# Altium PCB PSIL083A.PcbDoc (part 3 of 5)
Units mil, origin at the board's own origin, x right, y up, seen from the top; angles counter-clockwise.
Board outline 8750 x 2700 mil, 4 copper layers (Top Layer, Signal Layer 1, Signal Layer 2, Bottom Layer), stack 61.2 mil thick; 463 components, 395 nets, 2267 pads, 745 vias.
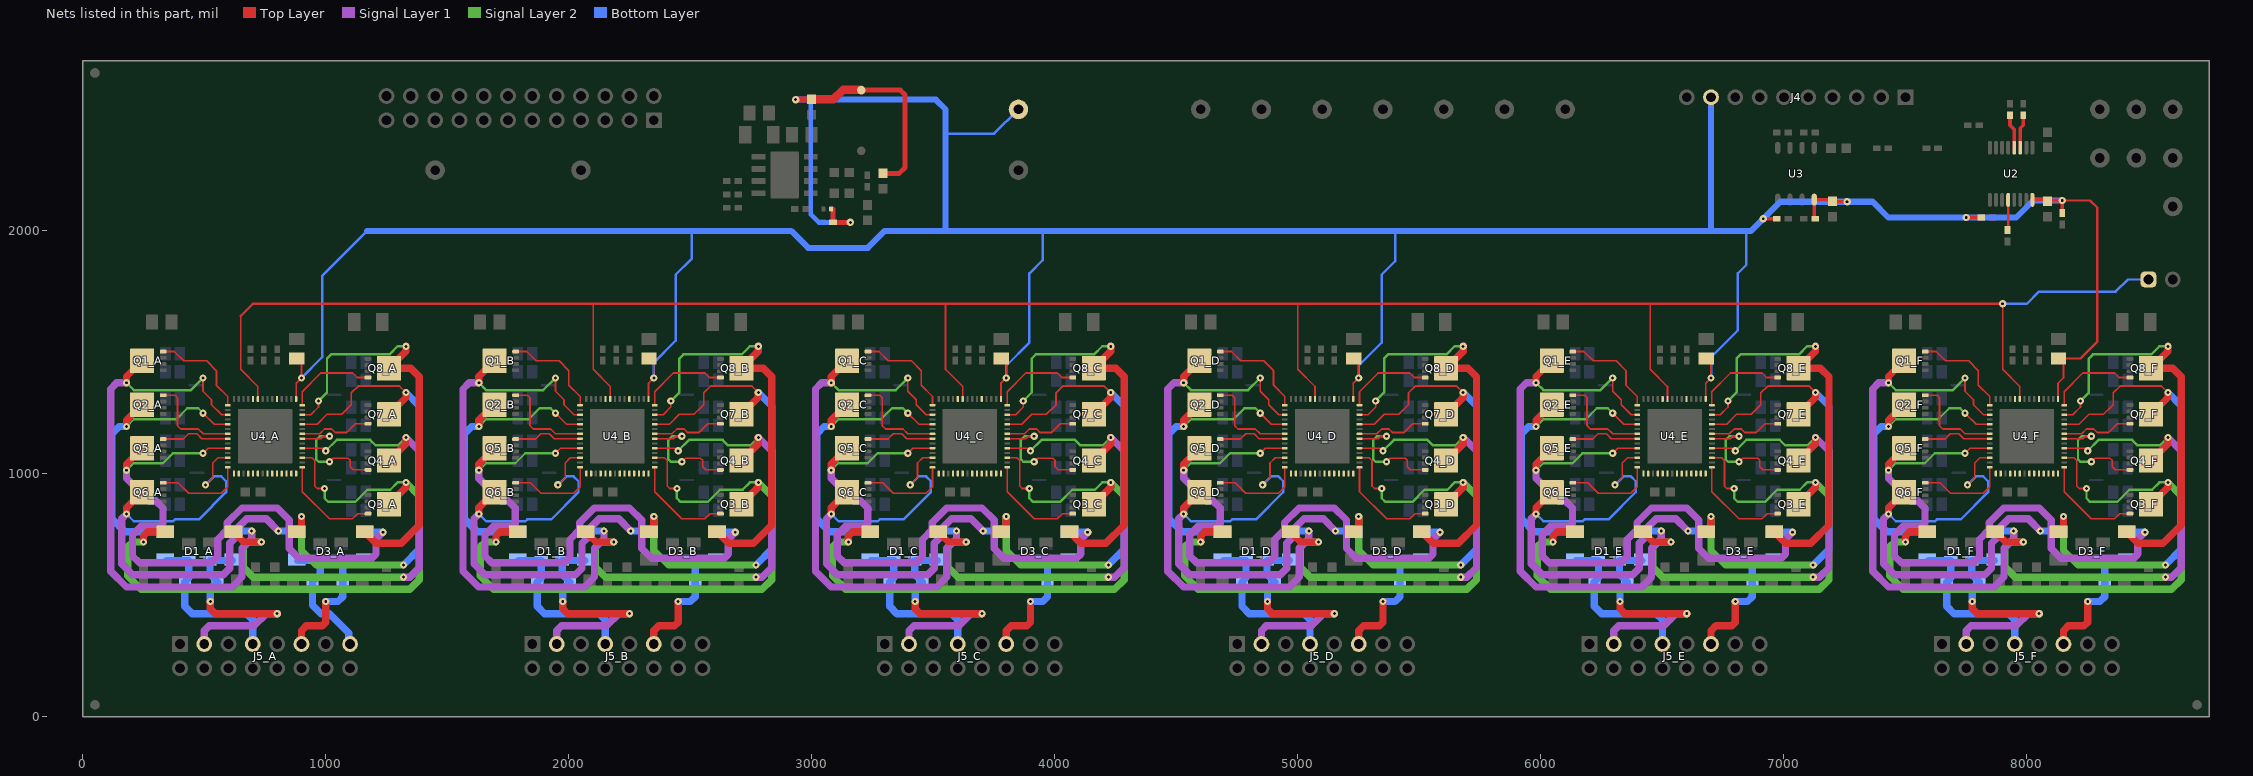
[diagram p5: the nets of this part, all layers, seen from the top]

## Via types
v1: diameter 30, hole 12, Top Layer to Bottom Layer, 610 vias
v2: diameter 19.68, hole 7.87, Top Layer to Bottom Layer, 130 vias
v3: diameter 19.68, hole 7.87, Top Layer to Bottom Layer, tented both sides, 4 vias
v4: diameter 34, hole 16, Top Layer to Bottom Layer, 1 vias

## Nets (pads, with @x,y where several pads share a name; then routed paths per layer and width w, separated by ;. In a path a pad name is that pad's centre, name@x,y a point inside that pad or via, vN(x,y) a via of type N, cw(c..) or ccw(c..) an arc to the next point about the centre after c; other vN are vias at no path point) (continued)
NetR36_2: R36.2 U2.3 | length 139.3
  Top Layer w15: U2.3@7972.5,2342.28 7972.5,2422.5 7985,2435 R36.2@7985,2476.38
NetR37_2: R37.2 U2.4 | length 141.3
  Top Layer w15: R37.2@7930,2476.38 7930,2435 7947.5,2417.5 U2.4@7947.5,2342.28
NetR38_1: R38.1 U2.12 | length 125.1
  Top Layer w10: R38.1@7920,2003.62 7922.5,2006.12 U2.12@7922.5,2127.72
NetU4_A_15: U4_A.15
NetU4_A_16: U4_A.16
NetU4_A_18: U4_A.18
NetU4_A_19: U4_A.19
NetU4_A_20: U4_A.20
NetU4_A_22: U4_A.22
NetU4_A_23: U4_A.23
NetU4_A_24: U4_A.24
NetU4_A_25: U4_A.25
NetU4_A_26: U4_A.26
NetU4_A_27: U4_A.27
NetU4_A_28: U4_A.28
NetU4_A_47: U4_A.47
NetU4_A_52: U4_A.52
NetU4_B_15: U4_B.15
NetU4_B_16: U4_B.16
NetU4_B_18: U4_B.18
NetU4_B_19: U4_B.19
NetU4_B_20: U4_B.20
NetU4_B_22: U4_B.22
NetU4_B_23: U4_B.23
NetU4_B_24: U4_B.24
NetU4_B_25: U4_B.25
NetU4_B_26: U4_B.26
NetU4_B_27: U4_B.27
NetU4_B_28: U4_B.28
NetU4_B_47: U4_B.47
NetU4_B_52: U4_B.52
NetU4_C_15: U4_C.15
NetU4_C_16: U4_C.16
NetU4_C_18: U4_C.18
NetU4_C_19: U4_C.19
NetU4_C_20: U4_C.20
NetU4_C_22: U4_C.22
NetU4_C_23: U4_C.23
NetU4_C_24: U4_C.24
NetU4_C_25: U4_C.25
NetU4_C_26: U4_C.26
NetU4_C_27: U4_C.27
NetU4_C_28: U4_C.28
NetU4_C_47: U4_C.47
NetU4_C_52: U4_C.52
NetU4_D_15: U4_D.15
NetU4_D_16: U4_D.16
NetU4_D_18: U4_D.18
NetU4_D_19: U4_D.19
NetU4_D_20: U4_D.20
NetU4_D_22: U4_D.22
NetU4_D_23: U4_D.23
NetU4_D_24: U4_D.24
NetU4_D_25: U4_D.25
NetU4_D_26: U4_D.26
NetU4_D_27: U4_D.27
NetU4_D_28: U4_D.28
NetU4_D_47: U4_D.47
NetU4_D_52: U4_D.52
NetU4_E_15: U4_E.15
NetU4_E_16: U4_E.16
NetU4_E_18: U4_E.18
NetU4_E_19: U4_E.19
NetU4_E_20: U4_E.20
NetU4_E_22: U4_E.22
NetU4_E_23: U4_E.23
NetU4_E_24: U4_E.24
NetU4_E_25: U4_E.25
NetU4_E_26: U4_E.26
NetU4_E_27: U4_E.27
NetU4_E_28: U4_E.28
NetU4_E_47: U4_E.47
NetU4_E_52: U4_E.52
NetU4_F_15: U4_F.15
NetU4_F_16: U4_F.16
NetU4_F_18: U4_F.18
NetU4_F_19: U4_F.19
NetU4_F_20: U4_F.20
NetU4_F_22: U4_F.22
NetU4_F_23: U4_F.23
NetU4_F_24: U4_F.24
NetU4_F_25: U4_F.25
NetU4_F_26: U4_F.26
NetU4_F_27: U4_F.27
NetU4_F_28: U4_F.28
NetU4_F_47: U4_F.47
NetU4_F_52: U4_F.52
PSE_3.3V: C8.1 C10.1 C12.1 C14_A.1 C14_B.1 C14_C.1 C14_D.1 C14_E.1 C14_F.1 C23.1 J4.9 L1.2 R3.1 R7.1 R8.2 R11.2 R12.2 R32.1 TP2.1 U2.16 U3.8 U4_A.43 U4_B.43 U4_C.43 U4_D.43 U4_E.43 U4_F.43 | length 16707.1
  Top Layer w7: U4_A.43@877.95,1308.54 877.95,1372.95 v1(900,1395) 900,1455 C14_A.1@880,1475 ; U4_B.43@2327.95,1308.54 2327.95,1372.95 v1(2350,1395) 2350,1455 C14_B.1@2330,1475 ; U4_C.43@3777.95,1308.54 3777.95,1372.95 v1(3800,1395) 3800,1455 C14_C.1@3780,1475 ; U4_D.43@5227.95,1308.54 5227.95,1372.95 v1(5250,1395) 5250,1455 C14_D.1@5230,1475 ; U4_E.43@6677.95,1308.54 6677.95,1372.95 v1(6700,1395) 6700,1455 C14_E.1@6680,1475 ; U4_F.43@8127.95,1308.54 8127.95,1372.95 8150,1395 8150,1455 C14_F.1@8130,1475
  Top Layer w10: C14_F.1@8130,1475 8220,1475 8290,1545 8290,2095 8260,2125 v1(8145,2125)
  Top Layer w15: v1(6915,2050) R12.2@6971.06,2050 ; R11.2@7128.31,2050 7124.69,2053.62 U3.8@7124.69,2128.7 7192.48,2128.7 C12.1@7199.69,2121.5 ; C12.1@7201.18,2120 v1(7260,2120) ; v1(7750,2055) R32.1@7811.38,2055 ; U2.16@8022.5,2127.72 8078.78,2127.72 C10.1@8085,2121.5 8088.5,2125 v1(8145,2125) R8.2@8145,2073.62
  Top Layer w20: 3086.93,2090 R3.1@3086.93,2035 v1(3158.31,2035) ; L1.2@3203.31,2579.02 3364.29,2579.02 3383.31,2560 3383.31,2260 3359.8,2236.5 C8.1@3293.31,2236.5
  Top Layer w25: v1(2933.31,2540) R7.1@2996.81,2540
  Top Layer w35: R7.1@2998.31,2541.5 3089.8,2541.5 3128.31,2580 3202.32,2580 L1.2@3203.31,2579.02
  Bottom Layer w10: v1(900,1395) 985,1480 985,1815 1170,2000 ; v1(2350,1395) 2350,1458.3 2440.25,1548.55 2440.25,1799.75 2440,1800 2440,1820 2505,1885 2505,2000 ; 3550,2400 3750,2400 TP2.1@3850,2500 ; v1(3800,1395) 3800,1445 3895,1540 3895,1825 3950,1880 3950,2000 ; v1(5250,1395) 5250,1445 5345,1540 5345,1820 5400,1875 5400,2000 ; v1(6700,1395) 6700,1480 6810,1590 6810,1825 6845,1860 6845,2000
  Bottom Layer w20: 2995.59,2538.78 2995.59,2067.72 3028.31,2035 v1(3158.31,2035)
  Bottom Layer w25: 1170,2000 2505,2000 2915,2000 2985,1930 3230,1930 3300,2000 3550,2000 ; v1(2933.31,2540) 3510,2540 3550,2500 3550,2400 3550,2000 ; J4.9@6700,2550 6700,2000 ; v1(8145,2125) 8025,2125 7955,2055 v1(7750,2055) 7430,2055 7365,2120 v1(7260,2120) 6985,2120 v1(6915,2050) 6865,2000 6845,2000 6700,2000 ; 3550,2000 3950,2000 5400,2000 6700,2000
PSE_A4_A: J2.1 U4_A.51 U4_B.51 U4_C.51 U4_D.51 U4_E.51 U4_F.51 | length 10386
  Top Layer w7: 650,1650 650,1430 720.47,1359.53 U4_A.51@720.47,1308.54 ; 2100,1700 2100,1430 2170.47,1359.53 U4_B.51@2170.47,1308.54 ; 3550,1700 3550,1430 3620.47,1359.53 U4_C.51@3620.47,1308.54 ; 5000,1700 5000,1430 5070.47,1359.53 U4_D.51@5070.47,1308.54 ; 6450,1700 6450,1430 6520.47,1359.53 U4_E.51@6520.47,1308.54 ; v1(7900,1700) 7900,1430 7970.47,1359.53 U4_F.51@7970.47,1308.54
  Top Layer w10: 650,1650 700,1700 v1(7900,1700)
  Bottom Layer w10: v1(7900,1700) 8000,1700 8050,1750 8365,1750 8415,1800 J2.1@8500,1800
PSE_D1_A: F1_A.2 Q1_A.5 Q1_A.6 Q1_A.7 Q1_A.8 Q1_A.9@244.61,1465 U4_A.3 | length 2364.4
  Top Layer w7: v1(495,1395) 495,1340 530,1305 530,1285 571.42,1243.58 U4_A.3@596.46,1243.58
  Top Layer w30: v1(180,1375) 180,1400.39 Q1_A.9@244.61,1465
  Signal Layer 1 w30: v1(180,1375) 140.33,1375 115,1349.67 115,600 180,535 615,535 655.43,575.43 655.43,694.17 695,733.74 v1(695,765)
  Signal Layer 2 w10: v1(180,1375) 210,1345 445,1345 v1(495,1395)
  Bottom Layer w30: F1_A.2@620,762.09 622.91,765 v1(695,765)
PSE_D1_B: F1_B.2 Q1_B.5 Q1_B.6 Q1_B.7 Q1_B.8 Q1_B.9@1694.61,1465 U4_B.3 | length 2364.4
  Top Layer w7: v1(1945,1395) 1945,1340 1980,1305 1980,1285 2021.42,1243.58 U4_B.3@2046.46,1243.58
  Top Layer w30: v1(1630,1375) 1630,1400.39 Q1_B.9@1694.61,1465
  Signal Layer 1 w30: v1(1630,1375) 1590.33,1375 1565,1349.67 1565,600 1630,535 2065,535 2105.43,575.43 2105.43,694.17 2145,733.74 v1(2145,765)
  Signal Layer 2 w10: v1(1630,1375) 1660,1345 1895,1345 v1(1945,1395)
  Bottom Layer w30: F1_B.2@2070,762.09 2072.91,765 v1(2145,765)
PSE_D1_C: F1_C.2 Q1_C.5 Q1_C.6 Q1_C.7 Q1_C.8 Q1_C.9@3144.61,1465 U4_C.3 | length 2364.4
  Top Layer w7: v1(3395,1395) 3395,1340 3430,1305 3430,1285 3471.42,1243.58 U4_C.3@3496.46,1243.58
  Top Layer w30: v1(3080,1375) 3080,1400.39 Q1_C.9@3144.61,1465
  Signal Layer 1 w30: v1(3080,1375) 3040.33,1375 3015,1349.67 3015,600 3080,535 3515,535 3555.43,575.43 3555.43,694.17 3595,733.74 v1(3595,765)
  Signal Layer 2 w10: v1(3080,1375) 3110,1345 3345,1345 v1(3395,1395)
  Bottom Layer w30: F1_C.2@3520,762.09 3522.91,765 v1(3595,765)
PSE_D1_D: F1_D.2 Q1_D.5 Q1_D.6 Q1_D.7 Q1_D.8 Q1_D.9@4594.61,1465 U4_D.3 | length 2364.4
  Top Layer w7: v1(4845,1395) 4845,1340 4880,1305 4880,1285 4921.42,1243.58 U4_D.3@4946.46,1243.58
  Top Layer w30: v1(4530,1375) 4530,1400.39 Q1_D.9@4594.61,1465
  Signal Layer 1 w30: v1(4530,1375) 4490.33,1375 4465,1349.67 4465,600 4530,535 4965,535 5005.43,575.43 5005.43,694.17 5045,733.74 v1(5045,765)
  Signal Layer 2 w10: v1(4530,1375) 4560,1345 4795,1345 v1(4845,1395)
  Bottom Layer w30: F1_D.2@4970,762.09 4972.91,765 v1(5045,765)
PSE_D1_E: F1_E.2 Q1_E.5 Q1_E.6 Q1_E.7 Q1_E.8 Q1_E.9@6044.61,1465 U4_E.3 | length 2364.4
  Top Layer w7: v1(6295,1395) 6295,1340 6330,1305 6330,1285 6371.42,1243.58 U4_E.3@6396.46,1243.58
  Top Layer w30: v1(5980,1375) 5980,1400.39 Q1_E.9@6044.61,1465
  Signal Layer 1 w30: v1(5980,1375) 5940.33,1375 5915,1349.67 5915,600 5980,535 6415,535 6455.43,575.43 6455.43,694.17 6495,733.74 v1(6495,765)
  Signal Layer 2 w10: v1(5980,1375) 6010,1345 6245,1345 v1(6295,1395)
  Bottom Layer w30: F1_E.2@6420,762.09 6422.91,765 v1(6495,765)
PSE_D1_F: F1_F.2 Q1_F.5 Q1_F.6 Q1_F.7 Q1_F.8 Q1_F.9@7494.61,1465 U4_F.3 | length 2364.4
  Top Layer w7: v1(7745,1395) 7745,1340 7780,1305 7780,1285 7821.42,1243.58 U4_F.3@7846.46,1243.58
  Top Layer w30: v1(7430,1375) 7430,1400.39 Q1_F.9@7494.61,1465
  Signal Layer 1 w30: v1(7430,1375) 7390.33,1375 7365,1349.67 7365,600 7430,535 7865,535 7905.43,575.43 7905.43,694.17 7945,733.74 v1(7945,765)
  Signal Layer 2 w10: v1(7430,1375) 7460,1345 7695,1345 v1(7745,1395)
  Bottom Layer w30: F1_F.2@7870,762.09 7872.91,765 v1(7945,765)
PSE_D2_A: F2_A.2 Q2_A.5 Q2_A.6 Q2_A.7 Q2_A.8 Q2_A.9@244.61,1285 U4_A.5 | length 1255.9
  Top Layer w7: v1(495,1250) 540.79,1204.21 U4_A.5@596.46,1204.21
  Top Layer w30: v1(180,1195) 180,1220.39 Q2_A.9@244.61,1285
  Signal Layer 2 w10: v1(180,1195) 210,1225 385,1225 430,1270 475,1270 v1(495,1250)
  Bottom Layer w30: v1(180,1195) 150,1195 120,1165 120,815 172.91,762.09 F2_A.2@340,762.09
PSE_D2_B: F2_B.2 Q2_B.5 Q2_B.6 Q2_B.7 Q2_B.8 Q2_B.9@1694.61,1285 U4_B.5 | length 1255.9
  Top Layer w7: v1(1945,1250) 1990.79,1204.21 U4_B.5@2046.46,1204.21
  Top Layer w30: v1(1630,1195) 1630,1220.39 Q2_B.9@1694.61,1285
  Signal Layer 2 w10: v1(1630,1195) 1660,1225 1835,1225 1880,1270 1925,1270 v1(1945,1250)
  Bottom Layer w30: v1(1630,1195) 1600,1195 1570,1165 1570,815 1622.91,762.09 F2_B.2@1790,762.09
PSE_D2_C: F2_C.2 Q2_C.5 Q2_C.6 Q2_C.7 Q2_C.8 Q2_C.9@3144.61,1285 U4_C.5 | length 1255.9
  Top Layer w7: v1(3395,1250) 3440.79,1204.21 U4_C.5@3496.46,1204.21
  Top Layer w30: v1(3080,1195) 3080,1220.39 Q2_C.9@3144.61,1285
  Signal Layer 2 w10: v1(3080,1195) 3110,1225 3285,1225 3330,1270 3375,1270 v1(3395,1250)
  Bottom Layer w30: v1(3080,1195) 3050,1195 3020,1165 3020,815 3072.91,762.09 F2_C.2@3240,762.09
PSE_D2_D: F2_D.2 Q2_D.5 Q2_D.6 Q2_D.7 Q2_D.8 Q2_D.9@4594.61,1285 U4_D.5 | length 1255.9
  Top Layer w7: v1(4845,1250) 4890.79,1204.21 U4_D.5@4946.46,1204.21
  Top Layer w30: v1(4530,1195) 4530,1220.39 Q2_D.9@4594.61,1285
  Signal Layer 2 w10: v1(4530,1195) 4560,1225 4735,1225 4780,1270 4825,1270 v1(4845,1250)
  Bottom Layer w30: v1(4530,1195) 4500,1195 4470,1165 4470,815 4522.91,762.09 F2_D.2@4690,762.09
PSE_D2_E: F2_E.2 Q2_E.5 Q2_E.6 Q2_E.7 Q2_E.8 Q2_E.9@6044.61,1285 U4_E.5 | length 1255.9
  Top Layer w7: v1(6295,1250) 6340.79,1204.21 U4_E.5@6396.46,1204.21
  Top Layer w30: v1(5980,1195) 5980,1220.39 Q2_E.9@6044.61,1285
  Signal Layer 2 w10: v1(5980,1195) 6010,1225 6185,1225 6230,1270 6275,1270 v1(6295,1250)
  Bottom Layer w30: v1(5980,1195) 5950,1195 5920,1165 5920,815 5972.91,762.09 F2_E.2@6140,762.09
PSE_D2_F: F2_F.2 Q2_F.5 Q2_F.6 Q2_F.7 Q2_F.8 Q2_F.9@7494.61,1285 U4_F.5 | length 1255.9
  Top Layer w7: v1(7745,1250) 7790.79,1204.21 U4_F.5@7846.46,1204.21
  Top Layer w30: v1(7430,1195) 7430,1220.39 Q2_F.9@7494.61,1285
  Signal Layer 2 w10: v1(7430,1195) 7460,1225 7635,1225 7680,1270 7725,1270 v1(7745,1250)
  Bottom Layer w30: v1(7430,1195) 7400,1195 7370,1165 7370,815 7422.91,762.09 F2_F.2@7590,762.09
PSE_D3_A: F5_A.2 Q5_A.5 Q5_A.6 Q5_A.7 Q5_A.8 Q5_A.9@244.61,1105 U4_A.10 | length 2600.7
  Top Layer w7: v1(495,1085) 515.79,1105.79 U4_A.10@596.46,1105.79
  Top Layer w30: v1(180,1015) 180,1040.39 Q5_A.9@244.61,1105
  Signal Layer 1 w30: v1(180,1015) 180,981.54 271.54,890 300,890 330,860 330,797.52 317.48,785 240,785 205,750 205,662.48 233.43,634.06 529.06,634.06 555,660 555,730.43 595,770.43 595,800 655,860 800,860 850,810 850,692.91 889.96,652.95 1189.21,652.95 1206.26,670 1206.26,731.26 v1(1235,760)
  Signal Layer 2 w10: v1(180,1015) 208.81,1043.81 329.6,1043.81 370.78,1085 v1(495,1085)
  Bottom Layer w30: F5_A.2@1162.09,760 v1(1235,760)
PSE_D3_B: F5_B.2 Q5_B.5 Q5_B.6 Q5_B.7 Q5_B.8 Q5_B.9@1694.61,1105 U4_B.10 | length 2600.7
  Top Layer w7: v1(1945,1085) 1965.79,1105.79 U4_B.10@2046.46,1105.79
  Top Layer w30: v1(1630,1015) 1630,1040.39 Q5_B.9@1694.61,1105
  Signal Layer 1 w30: v1(1630,1015) 1630,981.54 1721.54,890 1750,890 1780,860 1780,797.52 1767.48,785 1690,785 1655,750 1655,662.48 1683.43,634.06 1979.06,634.06 2005,660 2005,730.43 2045,770.43 2045,800 2105,860 2250,860 2300,810 2300,692.91 2339.96,652.95 2639.21,652.95 2656.26,670 2656.26,731.26 v1(2685,760)
  Signal Layer 2 w10: v1(1630,1015) 1658.81,1043.81 1779.6,1043.81 1820.78,1085 v1(1945,1085)
  Bottom Layer w30: F5_B.2@2612.09,760 v1(2685,760)
PSE_D3_C: F5_C.2 Q5_C.5 Q5_C.6 Q5_C.7 Q5_C.8 Q5_C.9@3144.61,1105 U4_C.10 | length 2600.7
  Top Layer w7: v1(3395,1085) 3415.79,1105.79 U4_C.10@3496.46,1105.79
  Top Layer w30: v1(3080,1015) 3080,1040.39 Q5_C.9@3144.61,1105
  Signal Layer 1 w30: v1(3080,1015) 3080,981.54 3171.54,890 3200,890 3230,860 3230,797.52 3217.48,785 3140,785 3105,750 3105,662.48 3133.43,634.06 3429.06,634.06 3455,660 3455,730.43 3495,770.43 3495,800 3555,860 3700,860 3750,810 3750,692.91 3789.96,652.95 4089.21,652.95 4106.26,670 4106.26,731.26 v1(4135,760)
  Signal Layer 2 w10: v1(3080,1015) 3108.81,1043.81 3229.6,1043.81 3270.78,1085 v1(3395,1085)
  Bottom Layer w30: F5_C.2@4062.09,760 v1(4135,760)
PSE_D3_D: F5_D.2 Q5_D.5 Q5_D.6 Q5_D.7 Q5_D.8 Q5_D.9@4594.61,1105 U4_D.10 | length 2600.7
  Top Layer w7: v1(4845,1085) 4865.79,1105.79 U4_D.10@4946.46,1105.79
  Top Layer w30: v1(4530,1015) 4530,1040.39 Q5_D.9@4594.61,1105
  Signal Layer 1 w30: v1(4530,1015) 4530,981.54 4621.54,890 4650,890 4680,860 4680,797.52 4667.48,785 4590,785 4555,750 4555,662.48 4583.43,634.06 4879.06,634.06 4905,660 4905,730.43 4945,770.43 4945,800 5005,860 5150,860 5200,810 5200,692.91 5239.96,652.95 5539.21,652.95 5556.26,670 5556.26,731.26 v1(5585,760)
  Signal Layer 2 w10: v1(4530,1015) 4558.81,1043.81 4679.6,1043.81 4720.78,1085 v1(4845,1085)
  Bottom Layer w30: F5_D.2@5512.09,760 v1(5585,760)
PSE_D3_E: F5_E.2 Q5_E.5 Q5_E.6 Q5_E.7 Q5_E.8 Q5_E.9@6044.61,1105 U4_E.10 | length 2600.7
  Top Layer w7: v1(6295,1085) 6315.79,1105.79 U4_E.10@6396.46,1105.79
  Top Layer w30: v1(5980,1015) 5980,1040.39 Q5_E.9@6044.61,1105
  Signal Layer 1 w30: v1(5980,1015) 5980,981.54 6071.54,890 6100,890 6130,860 6130,797.52 6117.48,785 6040,785 6005,750 6005,662.48 6033.43,634.06 6329.06,634.06 6355,660 6355,730.43 6395,770.43 6395,800 6455,860 6600,860 6650,810 6650,692.91 6689.96,652.95 6989.21,652.95 7006.26,670 7006.26,731.26 v1(7035,760)
  Signal Layer 2 w10: v1(5980,1015) 6008.81,1043.81 6129.6,1043.81 6170.78,1085 v1(6295,1085)
  Bottom Layer w30: F5_E.2@6962.09,760 v1(7035,760)
PSE_D3_F: F5_F.2 Q5_F.5 Q5_F.6 Q5_F.7 Q5_F.8 Q5_F.9@7494.61,1105 U4_F.10 | length 2600.7
  Top Layer w7: v1(7745,1085) 7765.79,1105.79 U4_F.10@7846.46,1105.79
  Top Layer w30: v1(7430,1015) 7430,1040.39 Q5_F.9@7494.61,1105
  Signal Layer 1 w30: v1(7430,1015) 7430,981.54 7521.54,890 7550,890 7580,860 7580,797.52 7567.48,785 7490,785 7455,750 7455,662.48 7483.43,634.06 7779.06,634.06 7805,660 7805,730.43 7845,770.43 7845,800 7905,860 8050,860 8100,810 8100,692.91 8139.96,652.95 8439.21,652.95 8456.26,670 8456.26,731.26 v1(8485,760)
  Signal Layer 2 w10: v1(7430,1015) 7458.81,1043.81 7579.6,1043.81 7620.78,1085 v1(7745,1085)
  Bottom Layer w30: F5_F.2@8412.09,760 v1(8485,760)
PSE_D4_A: F6_A.2 Q6_A.5 Q6_A.6 Q6_A.7 Q6_A.8 Q6_A.9@244.61,925 U4_A.12 | length 2061.2
  Top Layer w7: v1(505,955) 535,985 535,1045 556.42,1066.42 U4_A.12@596.46,1066.42
  Top Layer w30: v1(180,835) 180,860.39 Q6_A.9@244.61,925
  Signal Layer 1 w30: v1(180,835) 160,815 160,630 205,585 577.52,585 604.25,611.73 604.25,714.25 640,750 640,780 675,815 755,815 v1(805,765)
  Bottom Layer w10: v1(180,835) 210,805 371.82,805 379.49,812.68 477.68,812.68 590,925 590,970 570,990 540,990 v1(505,955)
  Bottom Layer w30: v1(805,765) 877.09,765 F6_A.2@880,762.09
PSE_D4_B: F6_B.2 Q6_B.5 Q6_B.6 Q6_B.7 Q6_B.8 Q6_B.9@1694.61,925 U4_B.12 | length 2061.2
  Top Layer w7: v1(1955,955) 1985,985 1985,1045 2006.42,1066.42 U4_B.12@2046.46,1066.42
  Top Layer w30: v1(1630,835) 1630,860.39 Q6_B.9@1694.61,925
  Signal Layer 1 w30: v1(1630,835) 1610,815 1610,630 1655,585 2027.52,585 2054.25,611.73 2054.25,714.25 2090,750 2090,780 2125,815 2205,815 v1(2255,765)
  Bottom Layer w10: v1(1630,835) 1660,805 1821.82,805 1829.49,812.68 1927.68,812.68 2040,925 2040,970 2020,990 1990,990 v1(1955,955)
  Bottom Layer w30: v1(2255,765) 2327.09,765 F6_B.2@2330,762.09
PSE_D4_C: F6_C.2 Q6_C.5 Q6_C.6 Q6_C.7 Q6_C.8 Q6_C.9@3144.61,925 U4_C.12 | length 2061.2
  Top Layer w7: v1(3405,955) 3435,985 3435,1045 3456.42,1066.42 U4_C.12@3496.46,1066.42
  Top Layer w30: v1(3080,835) 3080,860.39 Q6_C.9@3144.61,925
  Signal Layer 1 w30: v1(3080,835) 3060,815 3060,630 3105,585 3477.52,585 3504.25,611.73 3504.25,714.25 3540,750 3540,780 3575,815 3655,815 v1(3705,765)
  Bottom Layer w10: v1(3080,835) 3110,805 3271.82,805 3279.49,812.68 3377.68,812.68 3490,925 3490,970 3470,990 3440,990 v1(3405,955)
  Bottom Layer w30: v1(3705,765) 3777.09,765 F6_C.2@3780,762.09
PSE_D4_D: F6_D.2 Q6_D.5 Q6_D.6 Q6_D.7 Q6_D.8 Q6_D.9@4594.61,925 U4_D.12 | length 2061.2
  Top Layer w7: v1(4855,955) 4885,985 4885,1045 4906.42,1066.42 U4_D.12@4946.46,1066.42
  Top Layer w30: v1(4530,835) 4530,860.39 Q6_D.9@4594.61,925
  Signal Layer 1 w30: v1(4530,835) 4510,815 4510,630 4555,585 4927.52,585 4954.25,611.73 4954.25,714.25 4990,750 4990,780 5025,815 5105,815 v1(5155,765)
  Bottom Layer w10: v1(4530,835) 4560,805 4721.82,805 4729.49,812.68 4827.68,812.68 4940,925 4940,970 4920,990 4890,990 v1(4855,955)
  Bottom Layer w30: v1(5155,765) 5227.09,765 F6_D.2@5230,762.09
PSE_D4_E: F6_E.2 Q6_E.5 Q6_E.6 Q6_E.7 Q6_E.8 Q6_E.9@6044.61,925 U4_E.12 | length 2061.2
  Top Layer w7: v1(6305,955) 6335,985 6335,1045 6356.42,1066.42 U4_E.12@6396.46,1066.42
  Top Layer w30: v1(5980,835) 5980,860.39 Q6_E.9@6044.61,925
  Signal Layer 1 w30: v1(5980,835) 5960,815 5960,630 6005,585 6377.52,585 6404.25,611.73 6404.25,714.25 6440,750 6440,780 6475,815 6555,815 v1(6605,765)
  Bottom Layer w10: v1(5980,835) 6010,805 6171.82,805 6179.49,812.68 6277.68,812.68 6390,925 6390,970 6370,990 6340,990 v1(6305,955)
  Bottom Layer w30: v1(6605,765) 6677.09,765 F6_E.2@6680,762.09
PSE_D4_F: F6_F.2 Q6_F.5 Q6_F.6 Q6_F.7 Q6_F.8 Q6_F.9@7494.61,925 U4_F.12 | length 2061.2
  Top Layer w7: v1(7755,955) 7785,985 7785,1045 7806.42,1066.42 U4_F.12@7846.46,1066.42
  Top Layer w30: v1(7430,835) 7430,860.39 Q6_F.9@7494.61,925
  Signal Layer 1 w30: v1(7430,835) 7410,815 7410,630 7455,585 7827.52,585 7854.25,611.73 7854.25,714.25 7890,750 7890,780 7925,815 8005,815 v1(8055,765)
  Bottom Layer w10: v1(7430,835) 7460,805 7621.82,805 7629.49,812.68 7727.68,812.68 7840,925 7840,970 7820,990 7790,990 v1(7755,955)
  Bottom Layer w30: v1(8055,765) 8127.09,765 F6_F.2@8130,762.09
PSE_D5_A: F3_A.2 Q3_A.5 Q3_A.6 Q3_A.7 Q3_A.8 Q3_A.9@1260.39,875 U4_A.31 | length 2716
  Top Layer w7: U4_A.31@903.54,1066.42 943.58,1066.42 955,1055 955,950 965,940 v1(995,940)
  Top Layer w30: v1(250,720) 250,745 267.09,762.09 F3_A.2@340,762.09 ; Q3_A.9@1260.39,875 1330,944.61 v1(1330,965)
  Signal Layer 2 w10: v1(995,940) 995,900 1010,885 1121.5,885 1171.5,935 1265,935 1295,965 v1(1330,965)
  Signal Layer 2 w30: v1(250,720) 205,720 185,700 185,580 240,525 1345,525 1385,565 1385,910 v1(1330,965)
PSE_D5_B: F3_B.2 Q3_B.5 Q3_B.6 Q3_B.7 Q3_B.8 Q3_B.9@2710.39,875 U4_B.31 | length 2716
  Top Layer w7: U4_B.31@2353.54,1066.42 2393.58,1066.42 2405,1055 2405,950 2415,940 v1(2445,940)
  Top Layer w30: v1(1700,720) 1700,745 1717.09,762.09 F3_B.2@1790,762.09 ; Q3_B.9@2710.39,875 2780,944.61 v1(2780,965)
  Signal Layer 2 w10: v1(2445,940) 2445,900 2460,885 2571.5,885 2621.5,935 2715,935 2745,965 v1(2780,965)
  Signal Layer 2 w30: v1(1700,720) 1655,720 1635,700 1635,580 1690,525 2795,525 2835,565 2835,910 v1(2780,965)
PSE_D5_C: F3_C.2 Q3_C.5 Q3_C.6 Q3_C.7 Q3_C.8 Q3_C.9@4160.39,875 U4_C.31 | length 2716
  Top Layer w7: U4_C.31@3803.54,1066.42 3843.58,1066.42 3855,1055 3855,950 3865,940 v1(3895,940)
  Top Layer w30: v1(3150,720) 3150,745 3167.09,762.09 F3_C.2@3240,762.09 ; Q3_C.9@4160.39,875 4230,944.61 v1(4230,965)
  Signal Layer 2 w10: v1(3895,940) 3895,900 3910,885 4021.5,885 4071.5,935 4165,935 4195,965 v1(4230,965)
  Signal Layer 2 w30: v1(3150,720) 3105,720 3085,700 3085,580 3140,525 4245,525 4285,565 4285,910 v1(4230,965)
PSE_D5_D: F3_D.2 Q3_D.5 Q3_D.6 Q3_D.7 Q3_D.8 Q3_D.9@5610.39,875 U4_D.31 | length 2716
  Top Layer w7: U4_D.31@5253.54,1066.42 5293.58,1066.42 5305,1055 5305,950 5315,940 v1(5345,940)
  Top Layer w30: v1(4600,720) 4600,745 4617.09,762.09 F3_D.2@4690,762.09 ; Q3_D.9@5610.39,875 5680,944.61 v1(5680,965)
  Signal Layer 2 w10: v1(5345,940) 5345,900 5360,885 5471.5,885 5521.5,935 5615,935 5645,965 v1(5680,965)
  Signal Layer 2 w30: v1(4600,720) 4555,720 4535,700 4535,580 4590,525 5695,525 5735,565 5735,910 v1(5680,965)
PSE_D5_E: F3_E.2 Q3_E.5 Q3_E.6 Q3_E.7 Q3_E.8 Q3_E.9@7060.39,875 U4_E.31 | length 2716
  Top Layer w7: U4_E.31@6703.54,1066.42 6743.58,1066.42 6755,1055 6755,950 6765,940 v1(6795,940)
  Top Layer w30: v1(6050,720) 6050,745 6067.09,762.09 F3_E.2@6140,762.09 ; Q3_E.9@7060.39,875 7130,944.61 v1(7130,965)
  Signal Layer 2 w10: v1(6795,940) 6795,900 6810,885 6921.5,885 6971.5,935 7065,935 7095,965 v1(7130,965)
  Signal Layer 2 w30: v1(6050,720) 6005,720 5985,700 5985,580 6040,525 7145,525 7185,565 7185,910 v1(7130,965)
PSE_D5_F: F3_F.2 Q3_F.5 Q3_F.6 Q3_F.7 Q3_F.8 Q3_F.9@8510.39,875 U4_F.31 | length 2716
  Top Layer w7: U4_F.31@8153.54,1066.42 8193.58,1066.42 8205,1055 8205,950 8215,940 v1(8245,940)
  Top Layer w30: v1(7500,720) 7500,745 7517.09,762.09 F3_F.2@7590,762.09 ; Q3_F.9@8510.39,875 8580,944.61 v1(8580,965)
  Signal Layer 2 w10: v1(8245,940) 8245,900 8260,885 8371.5,885 8421.5,935 8515,935 8545,965 v1(8580,965)
  Signal Layer 2 w30: v1(7500,720) 7455,720 7435,700 7435,580 7490,525 8595,525 8635,565 8635,910 v1(8580,965)
PSE_D6_A: F4_A.2 Q4_A.5 Q4_A.6 Q4_A.7 Q4_A.8 Q4_A.9@1260.39,1055 U4_A.33 | length 2211.5
  Top Layer w7: U4_A.33@903.54,1105.79 989.21,1105.79 v1(1000,1095)
  Top Layer w30: F4_A.2@620,762.09 662.09,720 v1(735,720) ; Q4_A.9@1260.39,1055 1330,1124.61 v1(1330,1150)
  Signal Layer 1 w30: v1(1320,575) 1345,575 1385,615 1385,1095 v1(1330,1150)
  Signal Layer 2 w10: v1(1000,1095) 1045,1140 1182.6,1140 1205.37,1117.23 1297.23,1117.23 v1(1330,1150)
  Signal Layer 2 w30: v1(735,720) 681.26,720 660,698.74 660,616.3 701.3,575 v1(1320,575)
PSE_D6_B: F4_B.2 Q4_B.5 Q4_B.6 Q4_B.7 Q4_B.8 Q4_B.9@2710.39,1055 U4_B.33 | length 2211.5
  Top Layer w7: U4_B.33@2353.54,1105.79 2439.21,1105.79 v1(2450,1095)
  Top Layer w30: F4_B.2@2070,762.09 2112.09,720 v1(2185,720) ; Q4_B.9@2710.39,1055 2780,1124.61 v1(2780,1150)
  Signal Layer 1 w30: v1(2770,575) 2795,575 2835,615 2835,1095 v1(2780,1150)
  Signal Layer 2 w10: v1(2450,1095) 2495,1140 2632.6,1140 2655.37,1117.23 2747.23,1117.23 v1(2780,1150)
  Signal Layer 2 w30: v1(2185,720) 2131.26,720 2110,698.74 2110,616.3 2151.3,575 v1(2770,575)
PSE_D6_C: F4_C.2 Q4_C.5 Q4_C.6 Q4_C.7 Q4_C.8 Q4_C.9@4160.39,1055 U4_C.33 | length 2211.5
  Top Layer w7: U4_C.33@3803.54,1105.79 3889.21,1105.79 v1(3900,1095)
  Top Layer w30: F4_C.2@3520,762.09 3562.09,720 v1(3635,720) ; Q4_C.9@4160.39,1055 4230,1124.61 v1(4230,1150)
  Signal Layer 1 w30: v1(4220,575) 4245,575 4285,615 4285,1095 v1(4230,1150)
  Signal Layer 2 w10: v1(3900,1095) 3945,1140 4082.6,1140 4105.37,1117.23 4197.23,1117.23 v1(4230,1150)
  Signal Layer 2 w30: v1(3635,720) 3581.26,720 3560,698.74 3560,616.3 3601.3,575 v1(4220,575)
PSE_D6_D: F4_D.2 Q4_D.5 Q4_D.6 Q4_D.7 Q4_D.8 Q4_D.9@5610.39,1055 U4_D.33 | length 2211.5
  Top Layer w7: U4_D.33@5253.54,1105.79 5339.21,1105.79 v1(5350,1095)
  Top Layer w30: F4_D.2@4970,762.09 5012.09,720 v1(5085,720) ; Q4_D.9@5610.39,1055 5680,1124.61 v1(5680,1150)
  Signal Layer 1 w30: v1(5670,575) 5695,575 5735,615 5735,1095 v1(5680,1150)
  Signal Layer 2 w10: v1(5350,1095) 5395,1140 5532.6,1140 5555.37,1117.23 5647.23,1117.23 v1(5680,1150)
  Signal Layer 2 w30: v1(5085,720) 5031.26,720 5010,698.74 5010,616.3 5051.3,575 v1(5670,575)
PSE_D6_E: F4_E.2 Q4_E.5 Q4_E.6 Q4_E.7 Q4_E.8 Q4_E.9@7060.39,1055 U4_E.33 | length 2211.5
  Top Layer w7: U4_E.33@6703.54,1105.79 6789.21,1105.79 v1(6800,1095)
  Top Layer w30: F4_E.2@6420,762.09 6462.09,720 v1(6535,720) ; Q4_E.9@7060.39,1055 7130,1124.61 v1(7130,1150)
  Signal Layer 1 w30: v1(7120,575) 7145,575 7185,615 7185,1095 v1(7130,1150)
  Signal Layer 2 w10: v1(6800,1095) 6845,1140 6982.6,1140 7005.37,1117.23 7097.23,1117.23 v1(7130,1150)
  Signal Layer 2 w30: v1(6535,720) 6481.26,720 6460,698.74 6460,616.3 6501.3,575 v1(7120,575)
PSE_D6_F: F4_F.2 Q4_F.5 Q4_F.6 Q4_F.7 Q4_F.8 Q4_F.9@8510.39,1055 U4_F.33 | length 2211.5
  Top Layer w7: U4_F.33@8153.54,1105.79 8239.21,1105.79 v1(8250,1095)
  Top Layer w30: F4_F.2@7870,762.09 7912.09,720 v1(7985,720) ; Q4_F.9@8510.39,1055 8580,1124.61 v1(8580,1150)
  Signal Layer 1 w30: v1(8570,575) 8595,575 8635,615 8635,1095 v1(8580,1150)
  Signal Layer 2 w10: v1(8250,1095) 8295,1140 8432.6,1140 8455.37,1117.23 8547.23,1117.23 v1(8580,1150)
  Signal Layer 2 w30: v1(7985,720) 7931.26,720 7910,698.74 7910,616.3 7951.3,575 v1(8570,575)
PSE_D7_A: F7_A.2 Q7_A.5 Q7_A.6 Q7_A.7 Q7_A.8 Q7_A.9@1260.39,1245 U4_A.38 | length 2065.5
  Top Layer w7: U4_A.38@903.54,1204.21 964.21,1204.21 1005,1245 1065,1245 1105,1285 1105,1333.5 1132.87,1361.37 1303.63,1361.37 v1(1330,1335)
  Top Layer w30: F7_A.2@880,762.09 900,782.09 v1(900,825) ; Q7_A.9@1260.39,1245 1330,1314.61 v1(1330,1335)
  Signal Layer 2 w30: v1(900,825) 900,685 960,625 v1(1320,625)
  Bottom Layer w30: v1(1320,625) 1385,690 1385,1280 v1(1330,1335)
PSE_D7_B: F7_B.2 Q7_B.5 Q7_B.6 Q7_B.7 Q7_B.8 Q7_B.9@2710.39,1245 U4_B.38 | length 2065.5
  Top Layer w7: U4_B.38@2353.54,1204.21 2414.21,1204.21 2455,1245 2515,1245 2555,1285 2555,1333.5 2582.87,1361.37 2753.63,1361.37 v1(2780,1335)
  Top Layer w30: F7_B.2@2330,762.09 2350,782.09 v1(2350,825) ; Q7_B.9@2710.39,1245 2780,1314.61 v1(2780,1335)
  Signal Layer 2 w30: v1(2350,825) 2350,685 2410,625 v1(2770,625)
  Bottom Layer w30: v1(2770,625) 2835,690 2835,1280 v1(2780,1335)
PSE_D7_C: F7_C.2 Q7_C.5 Q7_C.6 Q7_C.7 Q7_C.8 Q7_C.9@4160.39,1245 U4_C.38 | length 2065.5
  Top Layer w7: U4_C.38@3803.54,1204.21 3864.21,1204.21 3905,1245 3965,1245 4005,1285 4005,1333.5 4032.87,1361.37 4203.63,1361.37 v1(4230,1335)
  Top Layer w30: F7_C.2@3780,762.09 3800,782.09 v1(3800,825) ; Q7_C.9@4160.39,1245 4230,1314.61 v1(4230,1335)
  Signal Layer 2 w30: v1(3800,825) 3800,685 3860,625 v1(4220,625)
  Bottom Layer w30: v1(4220,625) 4285,690 4285,1280 v1(4230,1335)
PSE_D7_D: F7_D.2 Q7_D.5 Q7_D.6 Q7_D.7 Q7_D.8 Q7_D.9@5610.39,1245 U4_D.38 | length 2065.5
  Top Layer w7: U4_D.38@5253.54,1204.21 5314.21,1204.21 5355,1245 5415,1245 5455,1285 5455,1333.5 5482.87,1361.37 5653.63,1361.37 v1(5680,1335)
  Top Layer w30: F7_D.2@5230,762.09 5250,782.09 v1(5250,825) ; Q7_D.9@5610.39,1245 5680,1314.61 v1(5680,1335)
  Signal Layer 2 w30: v1(5250,825) 5250,685 5310,625 v1(5670,625)
  Bottom Layer w30: v1(5670,625) 5735,690 5735,1280 v1(5680,1335)
PSE_D7_E: F7_E.2 Q7_E.5 Q7_E.6 Q7_E.7 Q7_E.8 Q7_E.9@7060.39,1245 U4_E.38 | length 2065.5
  Top Layer w7: U4_E.38@6703.54,1204.21 6764.21,1204.21 6805,1245 6865,1245 6905,1285 6905,1333.5 6932.87,1361.37 7103.63,1361.37 v1(7130,1335)
  Top Layer w30: F7_E.2@6680,762.09 6700,782.09 v1(6700,825) ; Q7_E.9@7060.39,1245 7130,1314.61 v1(7130,1335)
  Signal Layer 2 w30: v1(6700,825) 6700,685 6760,625 v1(7120,625)
  Bottom Layer w30: v1(7120,625) 7185,690 7185,1280 v1(7130,1335)
PSE_D7_F: F7_F.2 Q7_F.5 Q7_F.6 Q7_F.7 Q7_F.8 Q7_F.9@8510.39,1245 U4_F.38 | length 2065.5
  Top Layer w7: U4_F.38@8153.54,1204.21 8214.21,1204.21 8255,1245 8315,1245 8355,1285 8355,1333.5 8382.87,1361.37 8553.63,1361.37 v1(8580,1335)
  Top Layer w30: F7_F.2@8130,762.09 8150,782.09 v1(8150,825) ; Q7_F.9@8510.39,1245 8580,1314.61 v1(8580,1335)
  Signal Layer 2 w30: v1(8150,825) 8150,685 8210,625 v1(8570,625)
  Bottom Layer w30: v1(8570,625) 8635,690 8635,1280 v1(8580,1335)
PSE_D8_A: F8_A.2 Q8_A.5 Q8_A.6 Q8_A.7 Q8_A.8 Q8_A.9@1260.39,1435 U4_A.40 | length 1783.2
  Top Layer w7: U4_A.40@903.54,1243.58 938.58,1243.58 970,1275 v1(970,1300)
  Top Layer w30: F8_A.2@1160,762.09 1207.09,715 1310,715 1385,790 1385,1400 1350,1435 Q8_A.9@1260.39,1435 1330,1504.61 v1(1330,1525)
  Signal Layer 2 w10: v1(970,1300) 1005,1335 1005,1475 1021.5,1491.5 1261.5,1491.5 1295,1525 v1(1330,1525)
PSE_D8_B: F8_B.2 Q8_B.5 Q8_B.6 Q8_B.7 Q8_B.8 Q8_B.9@2710.39,1435 U4_B.40 | length 1783.2
  Top Layer w7: U4_B.40@2353.54,1243.58 2388.58,1243.58 2420,1275 v1(2420,1300)
  Top Layer w30: F8_B.2@2610,762.09 2657.09,715 2760,715 2835,790 2835,1400 2800,1435 Q8_B.9@2710.39,1435 2780,1504.61 v1(2780,1525)
  Signal Layer 2 w10: v1(2420,1300) 2455,1335 2455,1475 2471.5,1491.5 2711.5,1491.5 2745,1525 v1(2780,1525)
PSE_D8_C: F8_C.2 Q8_C.5 Q8_C.6 Q8_C.7 Q8_C.8 Q8_C.9@4160.39,1435 U4_C.40 | length 1783.2
  Top Layer w7: U4_C.40@3803.54,1243.58 3838.58,1243.58 3870,1275 v1(3870,1300)
  Top Layer w30: F8_C.2@4060,762.09 4107.09,715 4210,715 4285,790 4285,1400 4250,1435 Q8_C.9@4160.39,1435 4230,1504.61 v1(4230,1525)
  Signal Layer 2 w10: v1(3870,1300) 3905,1335 3905,1475 3921.5,1491.5 4161.5,1491.5 4195,1525 v1(4230,1525)
PSE_D8_D: F8_D.2 Q8_D.5 Q8_D.6 Q8_D.7 Q8_D.8 Q8_D.9@5610.39,1435 U4_D.40 | length 1783.2
  Top Layer w7: U4_D.40@5253.54,1243.58 5288.58,1243.58 5320,1275 v1(5320,1300)
  Top Layer w30: F8_D.2@5510,762.09 5557.09,715 5660,715 5735,790 5735,1400 5700,1435 Q8_D.9@5610.39,1435 5680,1504.61 v1(5680,1525)
  Signal Layer 2 w10: v1(5320,1300) 5355,1335 5355,1475 5371.5,1491.5 5611.5,1491.5 5645,1525 v1(5680,1525)
PSE_D8_E: F8_E.2 Q8_E.5 Q8_E.6 Q8_E.7 Q8_E.8 Q8_E.9@7060.39,1435 U4_E.40 | length 1783.2
  Top Layer w7: U4_E.40@6703.54,1243.58 6738.58,1243.58 6770,1275 v1(6770,1300)
  Top Layer w30: F8_E.2@6960,762.09 7007.09,715 7110,715 7185,790 7185,1400 7150,1435 Q8_E.9@7060.39,1435 7130,1504.61 v1(7130,1525)
  Signal Layer 2 w10: v1(6770,1300) 6805,1335 6805,1475 6821.5,1491.5 7061.5,1491.5 7095,1525 v1(7130,1525)
PSE_D8_F: F8_F.2 Q8_F.5 Q8_F.6 Q8_F.7 Q8_F.8 Q8_F.9@8510.39,1435 U4_F.40 | length 1783.2
  Top Layer w7: U4_F.40@8153.54,1243.58 8188.58,1243.58 8220,1275 v1(8220,1300)
  Top Layer w30: F8_F.2@8410,762.09 8457.09,715 8560,715 8635,790 8635,1400 8600,1435 Q8_F.9@8510.39,1435 8580,1504.61 v1(8580,1525)
  Signal Layer 2 w10: v1(8220,1300) 8255,1335 8255,1475 8271.5,1491.5 8511.5,1491.5 8545,1525 v1(8580,1525)
PSE_G1_A: Q1_A.4 U4_A.1 | length 412.7
  Top Layer w7: Q1_A.4@331.02,1503.39 376.61,1503.39 415,1465 510,1465 550,1425 550,1365 596.46,1318.54 U4_A.1@596.46,1282.95
PSE_G1_B: Q1_B.4 U4_B.1 | length 412.7
  Top Layer w7: Q1_B.4@1781.02,1503.39 1826.61,1503.39 1865,1465 1960,1465 2000,1425 2000,1365 2046.46,1318.54 U4_B.1@2046.46,1282.95
PSE_G1_C: Q1_C.4 U4_C.1 | length 412.7
  Top Layer w7: Q1_C.4@3231.02,1503.39 3276.61,1503.39 3315,1465 3410,1465 3450,1425 3450,1365 3496.46,1318.54 U4_C.1@3496.46,1282.95
PSE_G1_D: Q1_D.4 U4_D.1 | length 412.7
  Top Layer w7: Q1_D.4@4681.02,1503.39 4726.61,1503.39 4765,1465 4860,1465 4900,1425 4900,1365 4946.46,1318.54 U4_D.1@4946.46,1282.95
PSE_G1_E: Q1_E.4 U4_E.1 | length 412.7
  Top Layer w7: Q1_E.4@6131.02,1503.39 6176.61,1503.39 6215,1465 6310,1465 6350,1425 6350,1365 6396.46,1318.54 U4_E.1@6396.46,1282.95
PSE_G1_F: Q1_F.4 U4_F.1 | length 412.7
  Top Layer w7: Q1_F.4@7581.02,1503.39 7626.61,1503.39 7665,1465 7760,1465 7800,1425 7800,1365 7846.46,1318.54 U4_F.1@7846.46,1282.95
PSE_G2_A: Q2_A.4 U4_A.7 | length 398.7
  Top Layer w7: Q2_A.4@331.02,1323.39 380.16,1323.39 390,1313.54 390,1198.5 403.5,1185 475,1185 495.16,1164.84 U4_A.7@596.46,1164.84 U4_A.7@596.3,1165
PSE_G2_B: Q2_B.4 U4_B.7 | length 398.7
  Top Layer w7: Q2_B.4@1781.02,1323.39 1830.16,1323.39 1840,1313.54 1840,1198.5 1853.5,1185 1925,1185 1945.16,1164.84 U4_B.7@2046.46,1164.84 U4_B.7@2046.3,1165
PSE_G2_C: Q2_C.4 U4_C.7 | length 398.7
  Top Layer w7: Q2_C.4@3231.02,1323.39 3280.16,1323.39 3290,1313.54 3290,1198.5 3303.5,1185 3375,1185 3395.16,1164.84 U4_C.7@3496.46,1164.84 U4_C.7@3496.3,1165
PSE_G2_D: Q2_D.4 U4_D.7 | length 398.7
  Top Layer w7: Q2_D.4@4681.02,1323.39 4730.16,1323.39 4740,1313.54 4740,1198.5 4753.5,1185 4825,1185 4845.16,1164.84 U4_D.7@4946.46,1164.84 U4_D.7@4946.3,1165
PSE_G2_E: Q2_E.4 U4_E.7 | length 398.7
  Top Layer w7: Q2_E.4@6131.02,1323.39 6180.16,1323.39 6190,1313.54 6190,1198.5 6203.5,1185 6275,1185 6295.16,1164.84 U4_E.7@6396.46,1164.84 U4_E.7@6396.3,1165
PSE_G2_F: Q2_F.4 U4_F.7 | length 398.7
  Top Layer w7: Q2_F.4@7581.02,1323.39 7630.16,1323.39 7640,1313.54 7640,1198.5 7653.5,1185 7725,1185 7745.16,1164.84 U4_F.7@7846.46,1164.84 U4_F.7@7846.3,1165
PSE_G3_A: Q5_A.4 U4_A.8 | length 285.1
  Top Layer w7: Q5_A.4@332.8,1145.16 Q5_A.4@331.02,1143.39 413.39,1143.39 435,1165 470,1165 489.84,1145.16 U4_A.8@596.46,1145.16
PSE_G3_B: Q5_B.4 U4_B.8 | length 285.1
  Top Layer w7: Q5_B.4@1782.8,1145.16 Q5_B.4@1781.02,1143.39 1863.39,1143.39 1885,1165 1920,1165 1939.84,1145.16 U4_B.8@2046.46,1145.16
PSE_G3_C: Q5_C.4 U4_C.8 | length 285.1
  Top Layer w7: Q5_C.4@3232.8,1145.16 Q5_C.4@3231.02,1143.39 3313.39,1143.39 3335,1165 3370,1165 3389.84,1145.16 U4_C.8@3496.46,1145.16
PSE_G3_D: Q5_D.4 U4_D.8 | length 285.1
  Top Layer w7: Q5_D.4@4682.8,1145.16 Q5_D.4@4681.02,1143.39 4763.39,1143.39 4785,1165 4820,1165 4839.84,1145.16 U4_D.8@4946.46,1145.16
PSE_G3_E: Q5_E.4 U4_E.8 | length 285.1
  Top Layer w7: Q5_E.4@6132.8,1145.16 Q5_E.4@6131.02,1143.39 6213.39,1143.39 6235,1165 6270,1165 6289.84,1145.16 U4_E.8@6396.46,1145.16
PSE_G3_F: Q5_F.4 U4_F.8 | length 285.1
  Top Layer w7: Q5_F.4@7582.8,1145.16 Q5_F.4@7581.02,1143.39 7663.39,1143.39 7685,1165 7720,1165 7739.84,1145.16 U4_F.8@7846.46,1145.16
PSE_G4_A: Q6_A.4 U4_A.14 | length 375
  Top Layer w7: Q6_A.4@331.02,963.39 392.2,963.39 435.59,920 570,920 596.46,946.46 U4_A.14@596.46,1027.05
PSE_G4_B: Q6_B.4 U4_B.14 | length 375
  Top Layer w7: Q6_B.4@1781.02,963.39 1842.2,963.39 1885.59,920 2020,920 2046.46,946.46 U4_B.14@2046.46,1027.05
PSE_G4_C: Q6_C.4 U4_C.14 | length 375
  Top Layer w7: Q6_C.4@3231.02,963.39 3292.2,963.39 3335.59,920 3470,920 3496.46,946.46 U4_C.14@3496.46,1027.05
PSE_G4_D: Q6_D.4 U4_D.14 | length 375
  Top Layer w7: Q6_D.4@4681.02,963.39 4742.2,963.39 4785.59,920 4920,920 4946.46,946.46 U4_D.14@4946.46,1027.05
PSE_G4_E: Q6_E.4 U4_E.14 | length 375
  Top Layer w7: Q6_E.4@6131.02,963.39 6192.2,963.39 6235.59,920 6370,920 6396.46,946.46 U4_E.14@6396.46,1027.05
PSE_G4_F: Q6_F.4 U4_F.14 | length 375
  Top Layer w7: Q6_F.4@7581.02,963.39 7642.2,963.39 7685.59,920 7820,920 7846.46,946.46 U4_F.14@7846.46,1027.05
PSE_G5_A: Q3_A.4 U4_A.29 | length 426.1
  Top Layer w7: U4_A.29@903.54,1027.05 903.54,926.46 1015,815 1110,815 1131.61,836.61 Q3_A.4@1173.98,836.61
PSE_G5_B: Q3_B.4 U4_B.29 | length 426.1
  Top Layer w7: U4_B.29@2353.54,1027.05 2353.54,926.46 2465,815 2560,815 2581.61,836.61 Q3_B.4@2623.98,836.61
PSE_G5_C: Q3_C.4 U4_C.29 | length 426.1
  Top Layer w7: U4_C.29@3803.54,1027.05 3803.54,926.46 3915,815 4010,815 4031.61,836.61 Q3_C.4@4073.98,836.61
PSE_G5_D: Q3_D.4 U4_D.29 | length 426.1
  Top Layer w7: U4_D.29@5253.54,1027.05 5253.54,926.46 5365,815 5460,815 5481.61,836.61 Q3_D.4@5523.98,836.61
PSE_G5_E: Q3_E.4 U4_E.29 | length 426.1
  Top Layer w7: U4_E.29@6703.54,1027.05 6703.54,926.46 6815,815 6910,815 6931.61,836.61 Q3_E.4@6973.98,836.61
PSE_G5_F: Q3_F.4 U4_F.29 | length 426.1
  Top Layer w7: U4_F.29@8153.54,1027.05 8153.54,926.46 8265,815 8360,815 8381.61,836.61 Q3_F.4@8423.98,836.61
PSE_G6_A: Q4_A.4 U4_A.35 | length 517
  Top Layer w7: U4_A.35@903.54,1145.16 980.16,1145.16 990,1155 v1(1015,1155) ; v1(1015,1050) 1030,1065 1091.5,1065 1100.55,1055.95 1100.55,1028.86 1112.8,1016.61 Q4_A.4@1173.98,1016.61
  Signal Layer 2 w10: v1(1015,1050) 970,1050 960,1060 960,1140 975,1155 v1(1015,1155)
PSE_G6_B: Q4_B.4 U4_B.35 | length 517
  Top Layer w7: U4_B.35@2353.54,1145.16 2430.16,1145.16 2440,1155 v1(2465,1155) ; v1(2465,1050) 2480,1065 2541.5,1065 2550.55,1055.95 2550.55,1028.86 2562.8,1016.61 Q4_B.4@2623.98,1016.61
  Signal Layer 2 w10: v1(2465,1050) 2420,1050 2410,1060 2410,1140 2425,1155 v1(2465,1155)
PSE_G6_C: Q4_C.4 U4_C.35 | length 517
  Top Layer w7: U4_C.35@3803.54,1145.16 3880.16,1145.16 3890,1155 v1(3915,1155) ; v1(3915,1050) 3930,1065 3991.5,1065 4000.55,1055.95 4000.55,1028.86 4012.8,1016.61 Q4_C.4@4073.98,1016.61
  Signal Layer 2 w10: v1(3915,1050) 3870,1050 3860,1060 3860,1140 3875,1155 v1(3915,1155)
PSE_G6_D: Q4_D.4 U4_D.35 | length 517
  Top Layer w7: U4_D.35@5253.54,1145.16 5330.16,1145.16 5340,1155 v1(5365,1155) ; v1(5365,1050) 5380,1065 5441.5,1065 5450.55,1055.95 5450.55,1028.86 5462.8,1016.61 Q4_D.4@5523.98,1016.61
  Signal Layer 2 w10: v1(5365,1050) 5320,1050 5310,1060 5310,1140 5325,1155 v1(5365,1155)
PSE_G6_E: Q4_E.4 U4_E.35 | length 517
  Top Layer w7: U4_E.35@6703.54,1145.16 6780.16,1145.16 6790,1155 v1(6815,1155) ; v1(6815,1050) 6830,1065 6891.5,1065 6900.55,1055.95 6900.55,1028.86 6912.8,1016.61 Q4_E.4@6973.98,1016.61
  Signal Layer 2 w10: v1(6815,1050) 6770,1050 6760,1060 6760,1140 6775,1155 v1(6815,1155)
PSE_G6_F: Q4_F.4 U4_F.35 | length 517
  Top Layer w7: U4_F.35@8153.54,1145.16 8230.16,1145.16 8240,1155 v1(8265,1155) ; v1(8265,1050) 8280,1065 8341.5,1065 8350.55,1055.95 8350.55,1028.86 8362.8,1016.61 Q4_F.4@8423.98,1016.61
  Signal Layer 2 w10: v1(8265,1050) 8220,1050 8210,1060 8210,1140 8225,1155 v1(8265,1155)
PSE_G7_A: Q7_A.4 U4_A.36 | length 300.2
  Top Layer w7: U4_A.36@903.54,1164.84 974.84,1164.84 995,1185 1025,1185 1040,1170 1085.32,1170 1121.93,1206.61 Q7_A.4@1173.98,1206.61
PSE_G7_B: Q7_B.4 U4_B.36 | length 300.2
  Top Layer w7: U4_B.36@2353.54,1164.84 2424.84,1164.84 2445,1185 2475,1185 2490,1170 2535.32,1170 2571.93,1206.61 Q7_B.4@2623.98,1206.61
PSE_G7_C: Q7_C.4 U4_C.36 | length 300.2
  Top Layer w7: U4_C.36@3803.54,1164.84 3874.84,1164.84 3895,1185 3925,1185 3940,1170 3985.32,1170 4021.93,1206.61 Q7_C.4@4073.98,1206.61
PSE_G7_D: Q7_D.4 U4_D.36 | length 300.2
  Top Layer w7: U4_D.36@5253.54,1164.84 5324.84,1164.84 5345,1185 5375,1185 5390,1170 5435.32,1170 5471.93,1206.61 Q7_D.4@5523.98,1206.61
PSE_G7_E: Q7_E.4 U4_E.36 | length 300.2
  Top Layer w7: U4_E.36@6703.54,1164.84 6774.84,1164.84 6795,1185 6825,1185 6840,1170 6885.32,1170 6921.93,1206.61 Q7_E.4@6973.98,1206.61
PSE_G7_F: Q7_F.4 U4_F.36 | length 300.2
  Top Layer w7: U4_F.36@8153.54,1164.84 8224.84,1164.84 8245,1185 8275,1185 8290,1170 8335.32,1170 8371.93,1206.61 Q7_F.4@8423.98,1206.61
PSE_G8_A: Q8_A.4 U4_A.42 | length 367.4
  Top Layer w7: U4_A.42@905,1284.41 U4_A.42@903.54,1282.95 903.54,1338.54 980,1415 1110,1415 1128.39,1396.61 Q8_A.4@1173.98,1396.61
PSE_G8_B: Q8_B.4 U4_B.42 | length 367.4
  Top Layer w7: U4_B.42@2355,1284.41 U4_B.42@2353.54,1282.95 2353.54,1338.54 2430,1415 2560,1415 2578.39,1396.61 Q8_B.4@2623.98,1396.61
PSE_G8_C: Q8_C.4 U4_C.42 | length 367.4
  Top Layer w7: U4_C.42@3805,1284.41 U4_C.42@3803.54,1282.95 3803.54,1338.54 3880,1415 4010,1415 4028.39,1396.61 Q8_C.4@4073.98,1396.61
PSE_G8_D: Q8_D.4 U4_D.42 | length 367.4
  Top Layer w7: U4_D.42@5255,1284.41 U4_D.42@5253.54,1282.95 5253.54,1338.54 5330,1415 5460,1415 5478.39,1396.61 Q8_D.4@5523.98,1396.61
PSE_G8_E: Q8_E.4 U4_E.42 | length 367.4
  Top Layer w7: U4_E.42@6705,1284.41 U4_E.42@6703.54,1282.95 6703.54,1338.54 6780,1415 6910,1415 6928.39,1396.61 Q8_E.4@6973.98,1396.61
PSE_G8_F: Q8_F.4 U4_F.42 | length 367.4
  Top Layer w7: U4_F.42@8155,1284.41 U4_F.42@8153.54,1282.95 8153.54,1338.54 8230,1415 8360,1415 8378.39,1396.61 Q8_F.4@8423.98,1396.61
PSE_N1_A: C15_A.2 D1_A.2 F1_A.1 J5_A.3 | length 983.6
  Top Layer w30: v1(525,475) 525,445 545,425 v1(800,425)
  Signal Layer 1 w30: J5_A.3@500,300 500,355 520,375 705,375 755,425 v1(800,425)
  Bottom Layer w30: v1(525,475) 525,525 C15_A.2@555,555 523.31,586.69 D1_A.2@523.31,643.5 F1_A.1@615.59,643.5
PSE_N1_B: C15_B.2 D1_B.2 F1_B.1 J5_B.3 | length 983.6
  Top Layer w30: v1(1975,475) 1975,445 1995,425 v1(2250,425)
  Signal Layer 1 w30: J5_B.3@1950,300 1950,355 1970,375 2155,375 2205,425 v1(2250,425)
  Bottom Layer w30: v1(1975,475) 1975,525 C15_B.2@2005,555 1973.31,586.69 D1_B.2@1973.31,643.5 F1_B.1@2065.59,643.5
PSE_N1_C: C15_C.2 D1_C.2 F1_C.1 J5_C.3 | length 983.6
  Top Layer w30: v1(3425,475) 3425,445 3445,425 v1(3700,425)
  Signal Layer 1 w30: J5_C.3@3400,300 3400,355 3420,375 3605,375 3655,425 v1(3700,425)
  Bottom Layer w30: v1(3425,475) 3425,525 C15_C.2@3455,555 3423.31,586.69 D1_C.2@3423.31,643.5 F1_C.1@3515.59,643.5
PSE_N1_D: C15_D.2 D1_D.2 F1_D.1 J5_D.3 | length 983.6
  Top Layer w30: v1(4875,475) 4875,445 4895,425 v1(5150,425)
  Signal Layer 1 w30: J5_D.3@4850,300 4850,355 4870,375 5055,375 5105,425 v1(5150,425)
  Bottom Layer w30: v1(4875,475) 4875,525 C15_D.2@4905,555 4873.31,586.69 D1_D.2@4873.31,643.5 F1_D.1@4965.59,643.5
PSE_N1_E: C15_E.2 D1_E.2 F1_E.1 J5_E.3 | length 983.6
  Top Layer w30: v1(6325,475) 6325,445 6345,425 v1(6600,425)
  Signal Layer 1 w30: J5_E.3@6300,300 6300,355 6320,375 6505,375 6555,425 v1(6600,425)
  Bottom Layer w30: v1(6325,475) 6325,525 C15_E.2@6355,555 6323.31,586.69 D1_E.2@6323.31,643.5 F1_E.1@6415.59,643.5
PSE_N1_F: C15_F.2 D1_F.2 F1_F.1 J5_F.3 | length 983.6
  Top Layer w30: v1(7775,475) 7775,445 7795,425 v1(8050,425)
  Signal Layer 1 w30: J5_F.3@7750,300 7750,355 7770,375 7955,375 8005,425 v1(8050,425)
  Bottom Layer w30: v1(7775,475) 7775,525 C15_F.2@7805,555 7773.31,586.69 D1_F.2@7773.31,643.5 F1_F.1@7865.59,643.5
PSE_N2_A: C16_A.2 D1_A.3 F2_A.1 J5_A.7 | length 690.5
  Bottom Layer w30: F2_A.1@344.41,643.5 D1_A.3@436.69,643.5 436.69,571.69 C16_A.2@420,555 420,455 450,425 675,425 700,400 J5_A.7@700,300
PSE_N2_B: C16_B.2 D1_B.3 F2_B.1 J5_B.7 | length 690.5
  Bottom Layer w30: F2_B.1@1794.41,643.5 D1_B.3@1886.69,643.5 1886.69,571.69 C16_B.2@1870,555 1870,455 1900,425 2125,425 2150,400 J5_B.7@2150,300
PSE_N2_C: C16_C.2 D1_C.3 F2_C.1 J5_C.7 | length 690.5
  Bottom Layer w30: F2_C.1@3244.41,643.5 D1_C.3@3336.69,643.5 3336.69,571.69 C16_C.2@3320,555 3320,455 3350,425 3575,425 3600,400 J5_C.7@3600,300
PSE_N2_D: C16_D.2 D1_D.3 F2_D.1 J5_D.7 | length 690.5
  Bottom Layer w30: F2_D.1@4694.41,643.5 D1_D.3@4786.69,643.5 4786.69,571.69 C16_D.2@4770,555 4770,455 4800,425 5025,425 5050,400 J5_D.7@5050,300
PSE_N2_E: C16_E.2 D1_E.3 F2_E.1 J5_E.7 | length 690.5
  Bottom Layer w30: F2_E.1@6144.41,643.5 D1_E.3@6236.69,643.5 6236.69,571.69 C16_E.2@6220,555 6220,455 6250,425 6475,425 6500,400 J5_E.7@6500,300
PSE_N2_F: C16_F.2 D1_F.3 F2_F.1 J5_F.7 | length 690.5
  Bottom Layer w30: F2_F.1@7594.41,643.5 D1_F.3@7686.69,643.5 7686.69,571.69 C16_F.2@7670,555 7670,455 7700,425 7925,425 7950,400 J5_F.7@7950,300
PSE_N3_A: C19_A.2 D3_A.2 F5_A.1 J5_A.11 | length 566.9
  Top Layer w30: J5_A.11@900,300 900,355 920,375 985,375 1000,390 v1(1000,475)
  Bottom Layer w30: v1(1000,475) 1050,475 1070,495 C19_A.2@1070,555 D3_A.2@1070,636.81 ; D3_A.2@1063.31,643.5 F5_A.1@1155.59,643.5
PSE_N3_B: C19_B.2 D3_B.2 F5_B.1 J5_B.11 | length 566.9
  Top Layer w30: J5_B.11@2350,300 2350,355 2370,375 2435,375 2450,390 v1(2450,475)
  Bottom Layer w30: v1(2450,475) 2500,475 2520,495 C19_B.2@2520,555 D3_B.2@2520,636.81 ; D3_B.2@2513.31,643.5 F5_B.1@2605.59,643.5
PSE_N3_C: C19_C.2 D3_C.2 F5_C.1 J5_C.11 | length 566.9
  Top Layer w30: J5_C.11@3800,300 3800,355 3820,375 3885,375 3900,390 v1(3900,475)
  Bottom Layer w30: v1(3900,475) 3950,475 3970,495 C19_C.2@3970,555 D3_C.2@3970,636.81 ; D3_C.2@3963.31,643.5 F5_C.1@4055.59,643.5
PSE_N3_D: C19_D.2 D3_D.2 F5_D.1 J5_D.11 | length 566.9
  Top Layer w30: J5_D.11@5250,300 5250,355 5270,375 5335,375 5350,390 v1(5350,475)
  Bottom Layer w30: v1(5350,475) 5400,475 5420,495 C19_D.2@5420,555 D3_D.2@5420,636.81 ; D3_D.2@5413.31,643.5 F5_D.1@5505.59,643.5
PSE_N3_E: C19_E.2 D3_E.2 F5_E.1 J5_E.11 | length 566.9
  Top Layer w30: J5_E.11@6700,300 6700,355 6720,375 6785,375 6800,390 v1(6800,475)
  Bottom Layer w30: v1(6800,475) 6850,475 6870,495 C19_E.2@6870,555 D3_E.2@6870,636.81 ; D3_E.2@6863.31,643.5 F5_E.1@6955.59,643.5
PSE_N3_F: C19_F.2 D3_F.2 F5_F.1 J5_F.11 | length 566.9
  Top Layer w30: J5_F.11@8150,300 8150,355 8170,375 8235,375 8250,390 v1(8250,475)
  Bottom Layer w30: v1(8250,475) 8300,475 8320,495 C19_F.2@8320,555 D3_F.2@8320,636.81 ; D3_F.2@8313.31,643.5 F5_F.1@8405.59,643.5
PSE_N4_A: C20_A.2 D3_A.3 F6_A.1 J5_A.15 | length 533.6
  Bottom Layer w30: F6_A.1@884.41,643.5 D3_A.3@976.69,643.5 976.69,586.69 C20_A.2@945,555 945,460 980,425 1015,425 1095,345 1095,305 J5_A.15@1100,300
